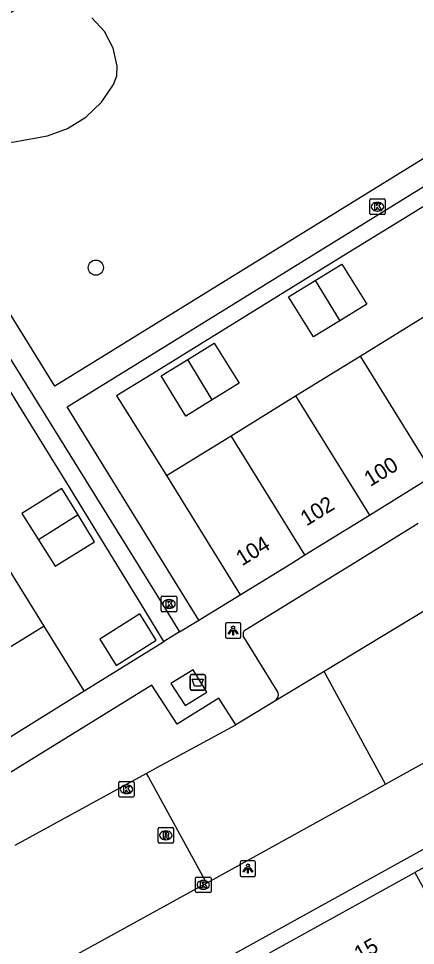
# Model space of a CAD drawing. Extents: x 159888 to 160757, y 384031 to 384746.
# Drawn here: x 160161.1 to 160186.6, y 384500.3 to 384560.1 of the extents above; entities that cross this region are included whole.
import ezdxf

# ---------------------------------------------------------------- set-up
doc = ezdxf.new("R2010")
doc.units = 0
for name, color, linetype in [('IMGEO_Afval_apart_plaats', 7, 'Continuous'), ('IMGEO_Boom', 7, 'Continuous'), ('IMGEO_Groenvoorziening', 7, 'Continuous'), ('IMGEO_Kolk', 7, 'Continuous'), ('IMGEO_Lichtpunt', 7, 'Continuous'), ('IMGEO_Pand', 7, 'Continuous'), ('IMGEO_Pand_nummerreeks', 7, 'Continuous'), ('IMGEO_Rijbaan_lokaal_open', 7, 'Continuous'), ('IMGEO_Rioolput', 7, 'Continuous'), ('IMGEO_Voetpad_gesloten', 7, 'Continuous'), ('IMGEO_Voetpad_open', 7, 'Continuous')]:
    doc.layers.add(name, color=color, linetype=linetype)

msp = doc.modelspace()

# ---------------------------------------------------------------- linework, layer by layer
at = {"layer": 'IMGEO_Afval_apart_plaats'}
for p, q in [((160172.125, 384516.884), (160172.125, 384517.684)), ((160172.125, 384517.684), (160172.125, 384516.884)), ((160172.225, 384517.784), (160173.015, 384517.784)), ((160173.015, 384517.784), (160172.225, 384517.784)), ((160173.115, 384517.684), (160173.115, 384516.884)), ((160173.115, 384516.884), (160173.115, 384517.684)), ((160173.015, 384516.784), (160172.225, 384516.784)), ((160172.225, 384516.784), (160173.015, 384516.784))]:
    msp.add_line(p, q, dxfattribs=at)
msp.add_lwpolyline([(160172.268, 384517.498), (160172.972, 384517.498), (160172.823, 384517.028), (160172.417, 384517.028), (160172.268, 384517.498)], dxfattribs=at)
for centre, start, end in [((160172.225, 384517.684), 90, 180), ((160172.225, 384517.684), 90, 180), ((160173.015, 384517.684), 0, 90), ((160173.015, 384517.684), 360, 90), ((160172.225, 384516.884), 180, 270), ((160172.225, 384516.884), 180, 270), ((160173.015, 384516.884), 270, 0), ((160173.015, 384516.884), 270, 0)]:
    msp.add_arc(centre, 0.1, start, end, dxfattribs=at)
at = {"layer": 'IMGEO_Boom'}
msp.add_circle((160166.053, 384544.009), 0.489, dxfattribs=at)
at = {"layer": 'IMGEO_Groenvoorziening'}
for points in [[(160217.276, 384566.598), (160214.703, 384564.976), (160211.144, 384562.778), (160206.438, 384559.861), (160202.905, 384557.7), (160198.249, 384554.781), (160194.673, 384552.612), (160189.978, 384549.717), (160186.466, 384547.528), (160181.751, 384544.625), (160178.213, 384542.424), (160173.521, 384539.537), (160169.984, 384537.335), (160167.391, 384535.745), (160167.622, 384535.376), (160170.612, 384530.605)], [(160160.832, 384560.601), (160159.184, 384559.601), (160157.679, 384558.409), (160156.914, 384557.513), (160156.396, 384556.407), (160156.195, 384555.201), (160156.316, 384554.03), (160156.614, 384553.304), (160157.149, 384552.677), (160157.857, 384552.252), (160158.621, 384552.079), (160160.802, 384552.108), (160162.949, 384552.494), (160164.227, 384552.975), (160165.406, 384553.716), (160166.412, 384554.681), (160167.187, 384555.805), (160167.398, 384556.377), (160167.429, 384556.987)], [(160167.429, 384556.987), (160167.161, 384558.149), (160166.602, 384559.224), (160165.805, 384560.11)], [(160170.433, 384519.911), (160169.216, 384521.94), (160166.364, 384526.593), (160164.187, 384530.138), (160161.258, 384534.862), (160159.072, 384538.41), (160156.136, 384543.082), (160153.968, 384546.63), (160151.058, 384551.349), (160148.865, 384554.895), (160147.274, 384557.486), (160142.113, 384554.255)]]:
    msp.add_lwpolyline(points, dxfattribs=at)
at = {"layer": 'IMGEO_Kolk'}
for p, q in [((160183.766, 384548.434), (160184.618, 384548.434)), ((160183.691, 384547.508), (160183.691, 384548.36)), ((160184.179, 384548.214), (160184.204, 384548.214)), ((160184.692, 384548.36), (160184.692, 384547.508)), ((160184.618, 384547.434), (160183.766, 384547.434)), ((160184.202, 384547.654), (160184.177, 384547.654)), ((160170.264, 384521.911), (160170.264, 384522.763)), ((160170.339, 384522.837), (160171.191, 384522.837)), ((160171.265, 384522.763), (160171.265, 384521.911)), ((160170.752, 384522.617), (160170.777, 384522.617)), ((160171.191, 384521.837), (160170.339, 384521.837)), ((160170.775, 384522.057), (160170.75, 384522.057)), ((160167.531, 384509.969), (160167.531, 384510.821)), ((160167.606, 384510.895), (160168.458, 384510.895)), ((160168.532, 384510.821), (160168.532, 384509.969)), ((160168.019, 384510.675), (160168.044, 384510.675)), ((160168.458, 384509.895), (160167.606, 384509.895)), ((160168.042, 384510.115), (160168.017, 384510.115)), ((160172.473, 384503.808), (160172.473, 384504.66)), ((160172.548, 384504.734), (160173.4, 384504.734)), ((160172.961, 384504.514), (160172.986, 384504.514)), ((160173.474, 384504.66), (160173.474, 384503.808)), ((160173.4, 384503.734), (160172.548, 384503.734)), ((160172.984, 384503.954), (160172.959, 384503.954))]:
    msp.add_line(p, q, dxfattribs=at)
for points in [[(160183.766, 384548.434), (160184.618, 384548.434)], [(160183.691, 384547.508), (160183.691, 384548.36)], [(160184.012, 384548.134), (160184.135, 384548.134), (160184.135, 384547.983), (160184.265, 384548.134), (160184.429, 384548.134), (160184.283, 384547.983), (160184.436, 384547.734), (160184.284, 384547.734), (160184.199, 384547.898), (160184.135, 384547.831), (160184.135, 384547.734), (160184.012, 384547.734), (160184.012, 384548.134)], [(160184.692, 384548.36), (160184.692, 384547.508)], [(160184.618, 384547.434), (160183.766, 384547.434)], [(160170.264, 384521.911), (160170.264, 384522.763)], [(160170.339, 384522.837), (160171.191, 384522.837)], [(160171.265, 384522.763), (160171.265, 384521.911)], [(160170.585, 384522.537), (160170.708, 384522.537), (160170.708, 384522.386), (160170.838, 384522.537), (160171.002, 384522.537), (160170.856, 384522.386), (160171.009, 384522.137), (160170.857, 384522.137), (160170.772, 384522.301), (160170.708, 384522.234), (160170.708, 384522.137), (160170.585, 384522.137), (160170.585, 384522.537)], [(160171.191, 384521.837), (160170.339, 384521.837)], [(160167.531, 384509.969), (160167.531, 384510.821)], [(160167.606, 384510.895), (160168.458, 384510.895)], [(160168.532, 384510.821), (160168.532, 384509.969)], [(160167.852, 384510.595), (160167.975, 384510.595), (160167.975, 384510.444), (160168.105, 384510.595), (160168.269, 384510.595), (160168.123, 384510.444), (160168.276, 384510.195), (160168.124, 384510.195), (160168.039, 384510.359), (160167.975, 384510.292), (160167.975, 384510.195), (160167.852, 384510.195), (160167.852, 384510.595)], [(160168.458, 384509.895), (160167.606, 384509.895)], [(160172.473, 384503.808), (160172.473, 384504.66)], [(160172.548, 384504.734), (160173.4, 384504.734)], [(160172.794, 384504.434), (160172.917, 384504.434), (160172.917, 384504.283), (160173.047, 384504.434), (160173.211, 384504.434), (160173.065, 384504.283), (160173.218, 384504.034), (160173.066, 384504.034), (160172.981, 384504.198), (160172.917, 384504.131), (160172.917, 384504.034), (160172.794, 384504.034), (160172.794, 384504.434)], [(160173.474, 384504.66), (160173.474, 384503.808)], [(160173.4, 384503.734), (160172.548, 384503.734)]]:
    msp.add_lwpolyline(points, dxfattribs=at)
for centre, start, end in [((160183.768, 384548.358), 91.55205, 178.44795), ((160183.768, 384548.358), 91.55205, 178.44795), ((160184.616, 384548.358), 1.55205, 88.44795), ((160184.616, 384548.358), 1.55205, 88.44795), ((160183.768, 384547.51), 181.55205, 268.44795), ((160183.768, 384547.51), 181.55205, 268.44795), ((160184.616, 384547.51), 271.55205, 358.44795), ((160184.616, 384547.51), 271.55205, 358.44795), ((160170.341, 384522.761), 91.55205, 178.44795), ((160170.341, 384522.761), 91.55205, 178.44795), ((160171.189, 384522.761), 1.55205, 88.44795), ((160171.189, 384522.761), 1.55205, 88.44795), ((160170.341, 384521.913), 181.55205, 268.44795), ((160170.341, 384521.913), 181.55205, 268.44795), ((160171.189, 384521.913), 271.55205, 358.44795), ((160171.189, 384521.913), 271.55205, 358.44795), ((160167.608, 384510.819), 91.55205, 178.44795), ((160167.608, 384510.819), 91.55205, 178.44795), ((160168.456, 384510.819), 1.55205, 88.44795), ((160168.456, 384510.819), 1.55205, 88.44795), ((160167.608, 384509.971), 181.55205, 268.44795), ((160167.608, 384509.971), 181.55205, 268.44795), ((160168.456, 384509.971), 271.55205, 358.44795), ((160168.456, 384509.971), 271.55205, 358.44795), ((160172.55, 384504.658), 91.55205, 178.44795), ((160172.55, 384504.658), 91.55205, 178.44795), ((160173.398, 384504.658), 1.55205, 88.44795), ((160173.398, 384504.658), 1.55205, 88.44795), ((160172.55, 384503.81), 181.55205, 268.44795), ((160172.55, 384503.81), 181.55205, 268.44795), ((160173.398, 384503.81), 271.55205, 358.44795), ((160173.398, 384503.81), 271.55205, 358.44795)]:
    msp.add_arc(centre, 0.0765, start, end, dxfattribs=at)
for centre, major_axis, ratio, start_param, end_param in [((160184.178, 384547.934), (-0.387, 0.002), 0.722429, 4.712389, 7.853982), ((160184.203, 384547.934), (-0.39, 0.002), 0.717154, 1.570796, 4.712389), ((160170.751, 384522.337), (-0.387, 0.002), 0.722429, 4.712389, 7.853982), ((160170.776, 384522.337), (-0.39, 0.002), 0.717154, 1.570796, 4.712389), ((160168.018, 384510.395), (-0.387, 0.002), 0.722429, 4.712389, 7.853982), ((160168.043, 384510.395), (-0.39, 0.002), 0.717154, 1.570796, 4.712389), ((160172.96, 384504.234), (-0.387, 0.002), 0.722429, 4.712389, 7.853982), ((160172.985, 384504.234), (-0.39, 0.002), 0.717154, 1.570796, 4.712389)]:
    msp.add_ellipse(centre, major_axis=major_axis, ratio=ratio, start_param=start_param, end_param=end_param, dxfattribs=at)
at = {"layer": 'IMGEO_Lichtpunt'}
for p, q in [((160174.396, 384521.024), (160174.396, 384520.217)), ((160174.396, 384521.024), (160174.396, 384520.217)), ((160175.298, 384521.119), (160174.49, 384521.119)), ((160175.298, 384521.119), (160174.49, 384521.119)), ((160175.392, 384520.217), (160175.392, 384521.024)), ((160175.392, 384520.217), (160175.392, 384521.024)), ((160174.49, 384520.123), (160175.298, 384520.123)), ((160174.49, 384520.123), (160175.298, 384520.123)), ((160175.346, 384505.683), (160175.346, 384504.876)), ((160175.346, 384505.683), (160175.346, 384504.876)), ((160176.248, 384505.778), (160175.44, 384505.778)), ((160176.248, 384505.778), (160175.44, 384505.778)), ((160176.342, 384504.876), (160176.342, 384505.683)), ((160176.342, 384504.876), (160176.342, 384505.683)), ((160175.44, 384504.782), (160176.248, 384504.782)), ((160175.44, 384504.782), (160176.248, 384504.782))]:
    msp.add_line(p, q, dxfattribs=at)
for points in [[(160174.77, 384520.688), (160174.809, 384520.66), (160174.621, 384520.398), (160174.583, 384520.425), (160174.77, 384520.688)], [(160174.872, 384520.64), (160174.919, 384520.64), (160174.919, 384520.318), (160174.872, 384520.318), (160174.872, 384520.64)], [(160174.982, 384520.66), (160175.02, 384520.687), (160175.207, 384520.425), (160175.168, 384520.397), (160174.982, 384520.66)], [(160175.72, 384505.347), (160175.759, 384505.319), (160175.571, 384505.057), (160175.533, 384505.084), (160175.72, 384505.347)], [(160175.822, 384505.299), (160175.869, 384505.299), (160175.869, 384504.977), (160175.822, 384504.977), (160175.822, 384505.299)], [(160175.932, 384505.319), (160175.97, 384505.346), (160176.157, 384505.084), (160176.118, 384505.056), (160175.932, 384505.319)]]:
    msp.add_lwpolyline(points, dxfattribs=at)
for centre in [(160174.895, 384520.822), (160175.845, 384505.481)]:
    msp.add_circle(centre, 0.0994, dxfattribs=at)
for centre, start, end in [((160174.49, 384521.024), 90, 180), ((160174.49, 384521.024), 90, 180), ((160175.298, 384521.024), 0, 90), ((160175.298, 384521.024), 0, 90), ((160174.49, 384520.217), 180, 270), ((160174.49, 384520.217), 180, 270), ((160175.298, 384520.217), 270, 0), ((160175.298, 384520.217), 270, 360), ((160175.44, 384505.683), 90, 180), ((160175.44, 384505.683), 90, 180), ((160176.248, 384505.683), 0, 90), ((160176.248, 384505.683), 0, 90), ((160175.44, 384504.876), 180, 270), ((160175.44, 384504.876), 180, 270), ((160176.248, 384504.876), 270, 0), ((160176.248, 384504.876), 270, 360)]:
    msp.add_arc(centre, 0.0946, start, end, dxfattribs=at)
at = {"layer": 'IMGEO_Pand'}
for points in [[(160180.179, 384543.176), (160181.894, 384544.231), (160183.501, 384541.653), (160181.77, 384540.59)], [(160181.77, 384540.59), (160180.06, 384539.541), (160178.464, 384542.121), (160180.179, 384543.176)], [(160180.179, 384543.176), (160181.77, 384540.59)], [(160183.074, 384538.312), (160187.228, 384540.881)], [(160171.969, 384538.09), (160173.684, 384539.139), (160175.276, 384536.562), (160173.552, 384535.5)], [(160178.92, 384535.743), (160183.074, 384538.312)], [(160183.074, 384538.312), (160187.822, 384530.635)], [(160173.552, 384535.5), (160171.841, 384534.446), (160170.253, 384537.041), (160171.969, 384538.09)], [(160173.552, 384535.5), (160171.969, 384538.09)], [(160174.766, 384533.174), (160178.92, 384535.743)], [(160178.92, 384535.743), (160183.668, 384528.065)], [(160170.612, 384530.605), (160174.766, 384533.174)], [(160179.515, 384525.495), (160174.766, 384533.174)], [(160170.612, 384530.605), (160175.354, 384522.92)], [(160183.668, 384528.065), (160187.822, 384530.635)], [(160164.91, 384528.069), (160163.861, 384529.78), (160161.288, 384528.174), (160162.357, 384526.469)], [(160164.91, 384528.069), (160162.357, 384526.469)], [(160162.357, 384526.469), (160163.427, 384524.763), (160165.974, 384526.334), (160164.91, 384528.069)], [(160179.515, 384525.495), (160183.668, 384528.065)], [(160162.734, 384520.915), (160160.157, 384525.082)], [(160175.354, 384522.92), (160178.674, 384524.974), (160179.515, 384525.495)], [(160169.95, 384520.003), (160168.88, 384521.692), (160166.302, 384520.058), (160167.372, 384518.369), (160169.95, 384520.003)], [(160162.734, 384520.915), (160155.075, 384516.177)], [(160165.312, 384516.747), (160162.734, 384520.915)], [(160157.662, 384511.995), (160165.312, 384516.747)], [(160203.556, 384502.837), (160196.415, 384509.815), (160196.075, 384510.23), (160186.593, 384505.023)], [(160177.056, 384499.746), (160177.514, 384500), (160186.593, 384505.023)], [(160186.593, 384505.023), (160190.804, 384497.414)]]:
    msp.add_lwpolyline(points, dxfattribs=at)
at = {"layer": 'IMGEO_Rijbaan_lokaal_open'}
for points in [[(160190.091, 384523.634), (160180.747, 384517.987)], [(160180.747, 384517.987), (160177.571, 384516.068)], [(160184.709, 384510.733), (160180.747, 384517.987)], [(160184.709, 384510.733), (160189.233, 384513.236), (160194.348, 384516.163), (160195.384, 384516.714)], [(160177.571, 384516.068), (160175.06, 384514.551)], [(160169.305, 384511.405), (160170.4, 384512.003), (160175.06, 384514.551)], [(160160.869, 384506.792), (160169.305, 384511.405)], [(160169.305, 384511.405), (160169.437, 384511.163), (160173.174, 384504.351)], [(160173.174, 384504.351), (160184.709, 384510.733)], [(160173.174, 384504.351), (160165.309, 384500), (160136.525, 384484.446), (160132.921, 384482.467), (160129.945, 384480.77)]]:
    msp.add_lwpolyline(points, dxfattribs=at)
at = {"layer": 'IMGEO_Rioolput'}
for p, q in [((160170.059, 384506.998), (160170.059, 384507.85)), ((160170.134, 384507.924), (160170.986, 384507.924)), ((160171.06, 384507.85), (160171.06, 384506.998)), ((160170.547, 384507.704), (160170.572, 384507.704)), ((160170.986, 384506.924), (160170.134, 384506.924)), ((160170.57, 384507.144), (160170.545, 384507.144))]:
    msp.add_line(p, q, dxfattribs=at)
for points in [[(160170.059, 384506.998), (160170.059, 384507.85)], [(160170.134, 384507.924), (160170.986, 384507.924)], [(160171.06, 384507.85), (160171.06, 384506.998)], [(160170.648, 384507.622), (160170.396, 384507.624), (160170.396, 384507.224)], [(160170.396, 384507.224), (160170.52, 384507.224), (160170.52, 384507.386), (160170.531, 384507.386)], [(160170.574, 384507.543), (160170.52, 384507.543), (160170.52, 384507.462)], [(160170.52, 384507.462), (160170.572, 384507.462)], [(160170.578, 384507.357), (160170.649, 384507.224), (160170.789, 384507.224), (160170.724, 384507.35)], [(160170.986, 384506.924), (160170.134, 384506.924)]]:
    msp.add_lwpolyline(points, dxfattribs=at)
for centre, radius, start, end in [((160170.136, 384507.848), 0.0765, 91.55205, 178.44795), ((160170.136, 384507.848), 0.0765, 91.55205, 178.44795), ((160170.984, 384507.848), 0.0765, 1.55205, 88.44795), ((160170.984, 384507.848), 0.0765, 1.55205, 88.44795), ((160170.53, 384507.333), 0.0533, 26.02933, 88.69889), ((160170.556, 384507.651), 0.19, 274.7715, 282.96867), ((160170.58, 384507.447), 0.0964, 77.00612, 93.18647), ((160170.594, 384507.504), 0.0378, 276.66336, 79.67722), ((160170.647, 384507.512), 0.109, 350.36119, 89.41601), ((160170.645, 384507.512), 0.112, 277.58423, 350.98172), ((160170.629, 384507.297), 0.108, 29.51342, 73.79051), ((160170.136, 384507), 0.0765, 181.55205, 268.44795), ((160170.136, 384507), 0.0765, 181.55205, 268.44795), ((160170.984, 384507), 0.0765, 271.55205, 358.44795), ((160170.984, 384507), 0.0765, 271.55205, 358.44795)]:
    msp.add_arc(centre, radius, start, end, dxfattribs=at)
for centre, major_axis, ratio, start_param, end_param in [((160170.546, 384507.424), (-0.387, 0.002), 0.722429, 4.712389, 7.853982), ((160170.571, 384507.424), (-0.39, 0.002), 0.717154, 1.570796, 4.712389)]:
    msp.add_ellipse(centre, major_axis=major_axis, ratio=ratio, start_param=start_param, end_param=end_param, dxfattribs=at)
at = {"layer": 'IMGEO_Voetpad_gesloten'}
msp.add_lwpolyline([(160171.8, 384515.802), (160173.195, 384516.657), (160172.332, 384518.094), (160170.883, 384517.21), (160171.8, 384515.802)], dxfattribs=at)
at = {"layer": 'IMGEO_Voetpad_open'}
for points in [[(160200.868, 384559.503), (160163.406, 384536.375), (160152.94, 384553.3), (160148.281, 384560.789), (160181.266, 384581.183), (160180.644, 384582.188), (160185.149, 384585.056), (160186.066, 384583.561), (160189.322, 384578.257), (160196.17, 384567.098), (160200.122, 384560.709)], [(160172.677, 384521.294), (160170.426, 384524.933), (160164.199, 384535.04), (160201.679, 384558.218), (160214.269, 384566.02), (160216.709, 384567.521)], [(160133.251, 384551.488), (160147, 384559.992), (160156.159, 384545.179), (160169.806, 384523.173), (160171.445, 384520.533)], [(160175.651, 384520.656), (160182.726, 384525.013), (160186.813, 384527.543)], [(160172.677, 384521.294), (160175.354, 384522.92)], [(160171.445, 384520.533), (160172.677, 384521.294)], [(160171.445, 384520.533), (160170.652, 384520.047), (160170.433, 384519.911)], [(160165.312, 384516.747), (160170.363, 384519.868), (160170.433, 384519.911)], [(160177.8, 384516.62), (160175.549, 384520.283)], [(160175.06, 384514.551), (160173.984, 384516.264), (160171.292, 384514.598), (160169.658, 384517.108), (160158.688, 384510.331)], [(160196.41, 384511.643), (160175.365, 384500), (160138.4, 384479.55), (160138.905, 384478.64)]]:
    msp.add_lwpolyline(points, dxfattribs=at)
for centre, radius, start, end in [((160175.886, 384520.391), 0.354, 131.62086, 197.79093), ((160177.283, 384516.511), 0.528, 303.00925, 11.92802)]:
    msp.add_arc(centre, radius, start, end, dxfattribs=at)

# ---------------------------------------------------------------- texts
at = {"layer": 'IMGEO_Pand_nummerreeks'}
for s, rotation, p in [('100', 31.75332, (160183.723, 384529.863)), ('102', 31.75332, (160179.619, 384527.323)), ('104', 31.74186, (160175.47, 384524.756)), ('11-15', 29.23282, (160181.356, 384498.326))]:
    msp.add_text(s, height=1, rotation=rotation, dxfattribs=at).set_placement(p)

doc.saveas('drawing.dxf')
